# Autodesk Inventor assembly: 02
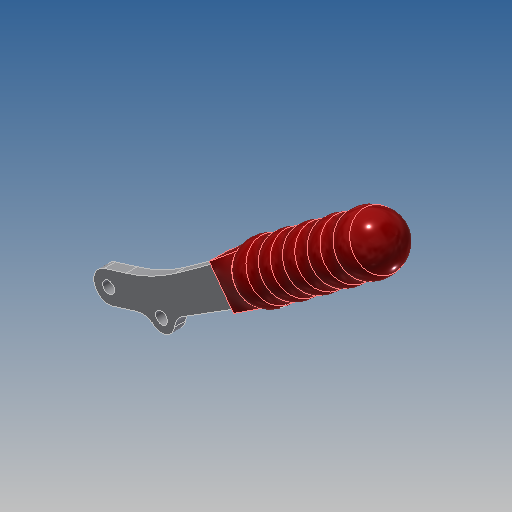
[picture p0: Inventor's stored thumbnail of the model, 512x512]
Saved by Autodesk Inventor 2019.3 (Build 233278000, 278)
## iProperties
Created: 2015-08
Part Number: 02
Material: Ogólny
Document SubType Name: Assembly
Designer: CADENGINEERING4
Author: CADENGINEERING4
Revision Number: ÈÎºÎ
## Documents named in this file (3)
- E:\STRONA\Horizontal toggle clamp\CH-203-P\02.iam
- E:\STRONA\Horizontal toggle clamp\CH-203-P\203-P-03.ipt
- E:\STRONA\Horizontal toggle clamp\CH-203-P\203-P-07.ipt
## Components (2 placed, 2 different names)
1. 203-P-03_15
2. 203-P-07_16
